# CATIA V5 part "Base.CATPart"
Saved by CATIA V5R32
Part number: Part1
Bounding box of the stored display mesh (mm): x -50 to 50, y -25 to 25, z 0 to 50
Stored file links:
  D:\PROJECTS\Project 2022\CATIA V5 6R 2022\Resources\Part Files\c12_catia_v5_6r2022_prt\c12_catia_v5-6r2022 figr_12-22\Base.CATPart
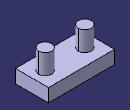
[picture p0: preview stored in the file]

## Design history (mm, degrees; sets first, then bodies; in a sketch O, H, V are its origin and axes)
Body1 (main body)
  Sketch1 on xy-plane, origin (0, 0, 0), H (1, 0, 0), V (0, 1, 0)
    line L1 (50, 25) -> (50, -25)
    line L2 (50, -25) -> (-50, -25)
    line L3 (-50, -25) -> (-50, 25)
    line L4 (-50, 25) -> (50, 25)
    circle A1 centre (-30, 0) radius 10
    point P5 (-30, 0)
    circle A2 centre (30, 0) radius 10
    length L2 = 100
    length L1 = 50
    radius A1 = 10
    distance P5 V = 30
    vertical: L1 V, L3 V
    horizontal: L2 H, L4 H
    equidistance: L1 L3 O, L2 L4 O
    coincidence: P5 H
    symmetry: A1 A2 V
  MultiPad1: profile Sketch1, domains (length 20; length 50; length 50)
